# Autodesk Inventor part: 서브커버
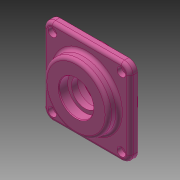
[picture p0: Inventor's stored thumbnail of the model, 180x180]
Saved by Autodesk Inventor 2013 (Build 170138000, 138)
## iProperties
Created: 2018-09
Part Number: 서브커버
Material: 알루미늄 6061
Document SubType Name: Modeling
Designer: mduedu
Density: 2.71 g/cm^3
Mass: 206.54 g
Surface Area: 196.569 cm^2
Volume: 76.2142 cm^3
Author: mduedu
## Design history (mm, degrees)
sketch "스케치1"
  geometry: L1 (-40, -40)-(40, -40); L2 (40, -40)-(40, 40); L3 (40, 40)-(-40, 40); L4 (-40, 40)-(-40, -40); L5 (-40, -40)-(40, 40); L6 (40, -40)-(-40, 40); 1 further point
  constraints: 12 end point, 2 midpoint, 2 parallel, 1 horizontal, 1 perpendicular
  dimensions: "d0" = 80 distance of L3.end L2.end; "d1" = 80 distance of L2.end L1.end
extrude "돌출1" new body sketch "스케치1" distance "d2" = 7; taper "d3" = 0 deg
sketch "스케치2"
  geometry: C1 r 30 at (0, 0); 1 further point
  constraints: 1 centre point, 1 coincident
  dimensions: "d4" = 60 diameter of C1
extrude "돌출2" join sketch "스케치2" distance "d5" = 10; taper "d6" = 0 deg
sketch "스케치3"
  geometry: C1 r 32.5 at (0, 0); 1 further point
  constraints: 1 centre point, 1 coincident
  dimensions: "d7" = 65 diameter of C1
extrude "돌출3" join sketch "스케치3" distance "d8" = 9; taper "d9" = 0 deg
sketch "스케치4"
  geometry: L1 (-32.5, -9)-(32.5, -9) reference; L2 (30, 17)-(-30, 17) reference; L3 (0, 17)-(0, -9); L4 (0, -9)-(20, -9); L5 (20, -9)-(20, 3); L6 (20, 3)-(0, 3); L7 (0, 3)-(0, -9); L8 (0, 3)-(12.5, 3); L9 (12.5, 3)-(12.5, 8.7); L10 (12.5, 8.7)-(0, 8.7); L11 (0, 8.7)-(0, 3); L12 (0, 8.7)-(16, 8.7); L13 (16, 8.7)-(16, 17); L14 (16, 17)-(0, 17); L15 (0, 17)-(0, 8.7); 1 further point
  constraints: 26 end point, 6 parallel, 3 horizontal, 3 perpendicular, 2 midpoint, 1 point on line
  dimensions: "d10" = 12 distance of L4.end L5.end; "d12" = 8.3 distance of L12.end L13.end; "d13" = 32 diameter of L13 L3; "d14" = 25 diameter of L9 L3; "d15" = 40 diameter of L5 L3
revolve "회전1" sketch "스케치4" stored, may be unused: angle "d16" = 90 deg
fillet "모깎기1" dims "d17" = 8
fillet "모깎기2" dims "d18" = 3
fillet "모깎기3" dims "d19" = 3
chamfer "모따기1" distance "d20" = 0.8; stored, may be unused: second distance "d21" = 2, angle "d22" = 30 deg
chamfer "모따기2" distance "d23" = 1; stored, may be unused: second distance "d24" = 2, angle "d25" = 30 deg
fillet "모깎기4" dims "d26" = 0.3
sketch "스케치5"
  geometry: A1 r 8 centre (-32, 32) between (-32, 40) and (-40, 32) reference; A2 r 8 centre (-32, -32) between (-40, -32) and (-32, -40) reference; A3 r 8 centre (32, -32) between (32, -40) and (40, -32) reference; A4 r 8 centre (32, 32) between (40, 32) and (32, 40) reference; 5 further points
  constraints: 4 coincident
hole "구멍1" sketch "스케치5" at (-32, 32), (32, 32), (32, -32), (-32, -32) diameter "d27" = 4.5; stored, may be unused: countersink angle "d31" = 90 deg, drill point angle "d33" = 118 deg; dims "d28" = 6, "d29" = 8, "d30" = 4.4, "d32" = 8
fillet "모깎기5" dims "d34" = 0.5
node "솔리드1"
